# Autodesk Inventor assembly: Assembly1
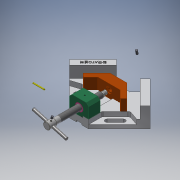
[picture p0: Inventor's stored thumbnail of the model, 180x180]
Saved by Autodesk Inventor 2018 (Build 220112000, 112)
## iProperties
Created: 2019-04
Part Number: Assembly1
Document SubType Name: Assembly
Designer: Administrator
Author: Administrator
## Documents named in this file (10)
- C:\Users\Administrator\Desktop\490408V1009\Assembly1.iam
- C:\Users\Administrator\Desktop\490408V1009\본체.ipt
- C:\Users\Administrator\Desktop\490408V1009\리드스크류.ipt
- C:\Users\Administrator\Desktop\490408V1009\서포트.ipt
- C:\Users\Administrator\Desktop\490408V1009\조.ipt
- C:\Users\Administrator\Desktop\490408V1009\부시.ipt
- C:\Users\Administrator\Desktop\490408V1009\핸들.ipt
- C:\Users\Administrator\Desktop\490408V1009\멈춤나사 M4x5.ipt
- C:\Users\Administrator\Desktop\490408V1009\멈춤나사 M4x10.ipt
- C:\Users\Administrator\Desktop\490408V1009\평행 핀 2.5x24.ipt
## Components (1 placed, 1 different names)
1. 핸들:1 — Mate:12, Mate:13
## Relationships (2: Mate 2)
- Mate:12: 핸들:1
- Mate:13: 핸들:1
